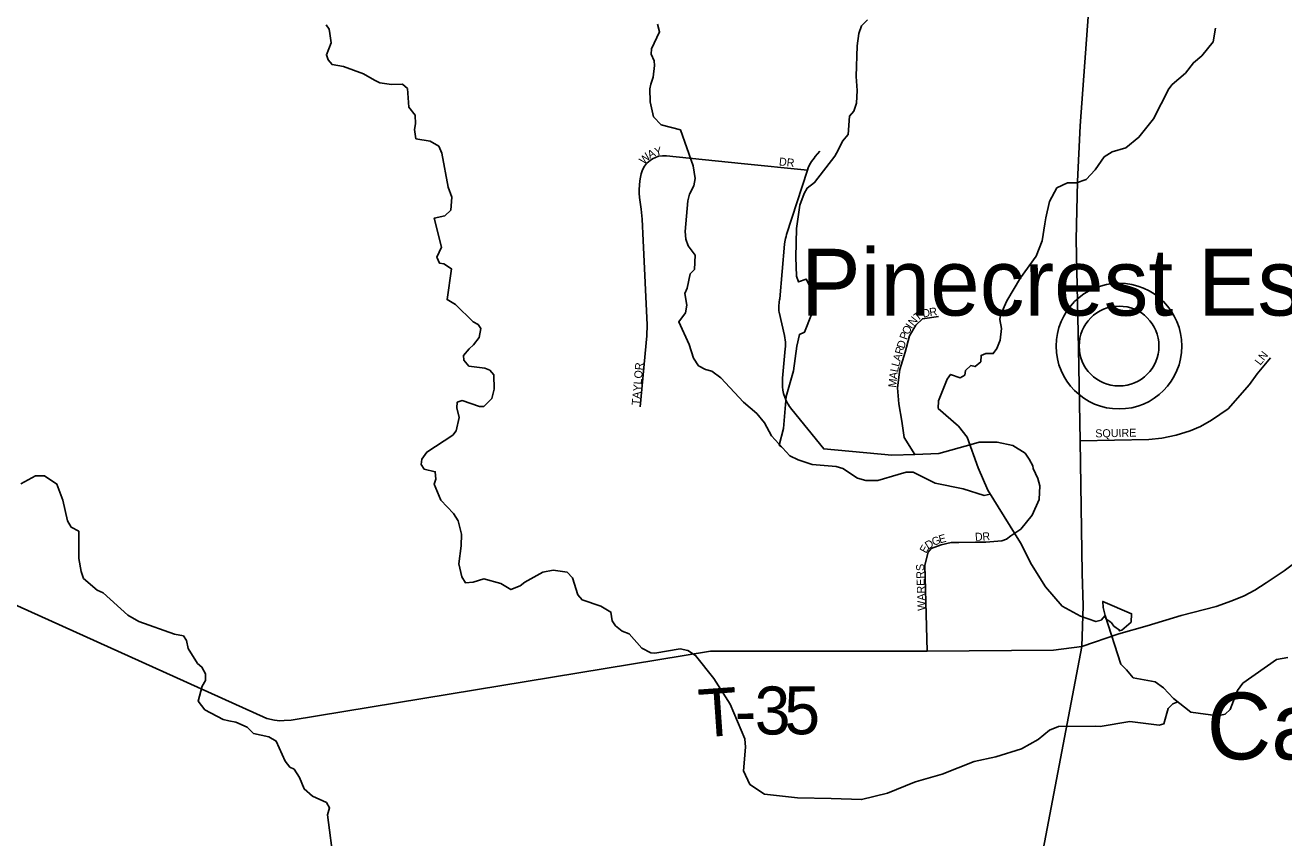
# Model space of a CAD drawing. Extents: x 0 to 40.4, y 0 to 22.
# Drawn here: x 3.509 to 4.998, y 17.952 to 18.913 of the extents above; entities that cross this region are included whole.
import ezdxf

# ---------------------------------------------------------------- set-up
doc = ezdxf.new("R2010")
doc.units = 0
for name, color, linetype in [('GM_X_Minor_Lake', 7, 'Continuous'), ('GM_X_Minor_River', 7, 'Continuous'), ('GM_X_State_Route', 7, 'Continuous'), ('GM_X_Township_Road', 7, 'Continuous'), ('GM_X_Township_Road_Text', 7, 'Continuous'), ('GM_X_Township_Subdivision', 7, 'Continuous'), ('GM_X_Township_Subdivision_Text', 7, 'Continuous'), ('GM_X_Unincorporated', 7, 'Continuous'), ('GM_X_Unincorporated_Text', 7, 'Continuous')]:
    doc.layers.add(name, color=color, linetype=linetype)

msp = doc.modelspace()

# ---------------------------------------------------------------- linework, layer by layer
at = {"layer": 'GM_X_Minor_Lake'}
for points in [[(4.8176, 18.2066), (4.818, 18.2168), (4.7839, 18.2314), (4.7843, 18.2242), (4.7869, 18.2147)], [(4.7869, 18.2147), (4.7877, 18.2109), (4.7922, 18.2075), (4.7941, 18.2059), (4.7971, 18.2021), (4.7998, 18.2002), (4.8035, 18.1979), (4.8035, 18.1964), (4.8066, 18.1972), (4.8176, 18.2066)]]:
    msp.add_lwpolyline(points, dxfattribs=at)
at = {"layer": 'GM_X_Minor_River'}
for points in [[(4.0095, 18.7212), (4.002, 18.7618), (3.9986, 18.7697), (3.9884, 18.7758), (3.9713, 18.7786), (3.9695, 18.7896), (3.971, 18.7964), (3.9703, 18.8066), (3.9631, 18.8161), (3.9613, 18.8381), (3.9556, 18.8431), (3.9423, 18.8428), (3.9287, 18.8447), (3.9223, 18.8481), (3.9094, 18.8554), (3.8855, 18.8642), (3.8722, 18.8665), (3.8677, 18.8722), (3.8655, 18.8779), (3.8712, 18.8923), (3.8697, 18.9033), (3.8686, 18.9083), (3.8652, 18.9136)], [(4.6509, 18.3582), (4.6436, 18.3567), (4.6186, 18.3647), (4.5856, 18.3713), (4.5595, 18.3843), (4.5512, 18.3843), (4.5417, 18.3813), (4.5177, 18.3742), (4.5037, 18.3742), (4.4938, 18.3773), (4.4764, 18.3884), (4.4685, 18.3911), (4.44, 18.3934), (4.4237, 18.3988), (4.4139, 18.4034), (4.392, 18.4274), (4.3837, 18.4426), (4.3746, 18.4536), (4.3591, 18.4669), (4.3319, 18.4958), (4.3213, 18.5038), (4.3141, 18.5058), (4.3058, 18.51), (4.2997, 18.5191), (4.2945, 18.5354), (4.2824, 18.562), (4.2904, 18.5726), (4.292, 18.5817), (4.2897, 18.5957), (4.2924, 18.6018), (4.2959, 18.6189), (4.3008, 18.6238), (4.3017, 18.6408), (4.2933, 18.6519), (4.2907, 18.6598), (4.29, 18.6689), (4.2932, 18.7053), (4.2951, 18.7133), (4.3, 18.7228), (4.3016, 18.7315), (4.2994, 18.7467), (4.2843, 18.7892), (4.2616, 18.7953), (4.2525, 18.8045), (4.2484, 18.8223), (4.2481, 18.8379), (4.2492, 18.8432), (4.2519, 18.8515), (4.2535, 18.8655), (4.2531, 18.8708), (4.2497, 18.8788), (4.2501, 18.8849), (4.2597, 18.9053), (4.2571, 18.9141)], [(4.4039, 18.4143), (4.401, 18.416), (4.4064, 18.4357), (4.4092, 18.4736), (4.418, 18.5043), (4.4219, 18.5334), (4.425, 18.5471), (4.4311, 18.5497), (4.4395, 18.5709), (4.4426, 18.5944), (4.4332, 18.6127), (4.4241, 18.6093), (4.4218, 18.6161), (4.4208, 18.6385), (4.4216, 18.6723), (4.4255, 18.6999), (4.4305, 18.7139), (4.4343, 18.7204), (4.4431, 18.7268), (4.4671, 18.7582), (4.4709, 18.765), (4.4759, 18.776), (4.4827, 18.7835), (4.4843, 18.8052), (4.4896, 18.8112), (4.4927, 18.8207), (4.4935, 18.8358), (4.4921, 18.8525), (4.4933, 18.8886), (4.4953, 18.903), (4.4987, 18.9121), (4.5056, 18.9192)], [(4.7869, 18.2147), (4.782, 18.209), (4.7759, 18.2075), (4.7577, 18.2137), (4.7361, 18.2259), (4.7161, 18.2487), (4.6995, 18.2749), (4.6867, 18.3008), (4.6478, 18.3631), (4.6365, 18.3893), (4.6234, 18.4258), (4.6132, 18.4387), (4.5893, 18.4596), (4.5898, 18.4687), (4.5997, 18.4941), (4.6039, 18.4998), (4.6153, 18.496), (4.6206, 18.499), (4.6217, 18.5047), (4.6278, 18.5103), (4.6328, 18.5092), (4.6396, 18.5148), (4.64, 18.5224), (4.6457, 18.5247), (4.6544, 18.5246), (4.6586, 18.5307), (4.6625, 18.5402), (4.664, 18.5542), (4.6622, 18.5648), (4.6629, 18.5701), (4.6706, 18.5868), (4.6866, 18.614), (4.7053, 18.6398), (4.7122, 18.6579), (4.7153, 18.678), (4.7164, 18.6852), (4.7211, 18.7046), (4.7298, 18.7205), (4.7424, 18.7265), (4.753, 18.7264), (4.7644, 18.7306), (4.7751, 18.7419), (4.7857, 18.7574), (4.7952, 18.7631), (4.8112, 18.7679), (4.8268, 18.7804), (4.8439, 18.8023), (4.8623, 18.8379), (4.8661, 18.8428), (4.8817, 18.8564), (4.8912, 18.8685), (4.9011, 18.8768), (4.9144, 18.8935), (4.9175, 18.9094)], [(4.8726, 18.1127), (4.867, 18.1101), (4.8613, 18.1048), (4.8563, 18.0866), (4.8506, 18.0851), (4.8161, 18.0894), (4.7808, 18.0835), (4.7758, 18.0839), (4.7315, 18.0833), (4.7208, 18.0791), (4.7075, 18.0678), (4.6877, 18.0569), (4.6574, 18.0475), (4.6319, 18.0419), (4.5939, 18.0269), (4.5662, 18.019), (4.5613, 18.0175), (4.5294, 18.0044), (4.4986, 17.9969), (4.4626, 17.9982), (4.4228, 17.9991), (4.3837, 18.0034), (4.3663, 18.0148), (4.3591, 18.0308), (4.3611, 18.0588), (4.3604, 18.0687), (4.3431, 18.1097), (4.3238, 18.1401), (4.3023, 18.1675), (4.2932, 18.1732), (4.2838, 18.1752), (4.2541, 18.1703), (4.2492, 18.1707), (4.2386, 18.1761), (4.2235, 18.1928), (4.2152, 18.1963), (4.2076, 18.2024), (4.2034, 18.2084), (4.202, 18.2187), (4.1902, 18.2259), (4.1679, 18.2332), (4.163, 18.2393), (4.1566, 18.2594), (4.1502, 18.2659), (4.1338, 18.2682), (4.1217, 18.266), (4.1004, 18.254), (4.0947, 18.2498), (4.0837, 18.2453), (4.072, 18.2525), (4.0519, 18.2579), (4.039, 18.2542), (4.0299, 18.2534), (4.0257, 18.2603), (4.022, 18.2759), (4.0247, 18.2971), (4.0251, 18.3107), (4.0214, 18.3267), (4.0157, 18.3354), (4.001, 18.351), (3.9931, 18.37), (3.995, 18.3761), (3.9943, 18.3848), (3.981, 18.3879), (3.9776, 18.3932), (3.9784, 18.3997), (3.9841, 18.408), (4.0149, 18.428), (4.0191, 18.4333), (4.0226, 18.4488), (4.0199, 18.4602), (4.0203, 18.467), (4.026, 18.4689), (4.0465, 18.462), (4.0518, 18.462), (4.0613, 18.4714), (4.064, 18.4824), (4.0637, 18.4995), (4.0588, 18.5048), (4.0527, 18.5071), (4.0341, 18.5098), (4.0281, 18.5167), (4.0277, 18.5224), (4.0342, 18.5303), (4.0395, 18.5348), (4.046, 18.5435), (4.048, 18.5541), (4.0449, 18.5591), (4.0389, 18.5621), (4.0181, 18.5827), (4.0082, 18.5884), (4.0133, 18.6248), (4.0042, 18.6305), (3.9993, 18.6313), (3.9963, 18.6385), (4.0016, 18.6503), (3.993, 18.6848), (4.0055, 18.6874), (4.0128, 18.6942), (4.014, 18.7094), (4.0095, 18.7212)], [(3.8743, 17.9214), (3.8666, 17.9787), (3.8692, 17.987), (3.8655, 17.9935), (3.8492, 18.0008), (3.8393, 18.0095), (3.8337, 18.0232), (3.8273, 18.0327), (3.822, 18.0354), (3.8167, 18.0422), (3.8062, 18.0661), (3.7975, 18.0711), (3.7793, 18.075), (3.7717, 18.0826), (3.7584, 18.0883), (3.7501, 18.0899), (3.7433, 18.0918), (3.7217, 18.1029), (3.7138, 18.1135), (3.7184, 18.1309), (3.7226, 18.1377), (3.7226, 18.1457), (3.7181, 18.1537), (3.7128, 18.1579), (3.7018, 18.1757), (3.7, 18.1852), (3.6962, 18.1906), (3.6856, 18.1925), (3.6435, 18.2074), (3.6307, 18.2151), (3.6015, 18.2413), (3.5943, 18.2448), (3.5781, 18.2585), (3.5754, 18.2668), (3.5725, 18.282), (3.5726, 18.3143), (3.5635, 18.3192), (3.5593, 18.3265), (3.5537, 18.3511), (3.5466, 18.3701), (3.5318, 18.3797), (3.5212, 18.3797), (3.5041, 18.3706)], [(4.92, 18.0959), (4.8882, 18.1005), (4.8678, 18.1165), (4.8557, 18.1291), (4.8458, 18.1363), (4.82, 18.141), (4.8121, 18.1505), (4.8053, 18.157), (4.7869, 18.2147)], [(5.003, 18.165), (4.9893, 18.1628), (4.9498, 18.1345), (4.9433, 18.1258), (4.9345, 18.1034), (4.9288, 18.0981), (4.92, 18.0959)]]:
    msp.add_lwpolyline(points, dxfattribs=at)
at = {"layer": 'GM_X_State_Route'}
msp.add_lwpolyline([(4.8369, 19.8987), (4.804, 19.4399), (4.791, 19.2678), (4.7732, 19.0147), (4.7573, 18.794), (4.7539, 18.7281), (4.7525, 18.6596), (4.7554, 18.5304), (4.7572, 18.4214), (4.7597, 18.2646), (4.7608, 18.2263), (4.759, 18.178), (4.7164, 17.9544), (4.6792, 17.7593)], dxfattribs=at)
at = {"layer": 'GM_X_Township_Road'}
for points in [[(6.1264, 18.8144), (5.7095, 18.6233), (5.6523, 18.5981), (5.3968, 18.4728), (5.2841, 18.4312), (5.2746, 18.429), (5.2643, 18.4248), (5.2567, 18.4218), (5.2483, 18.4173), (5.2376, 18.4113), (5.1965, 18.393), (5.0945, 18.335), (5.0605, 18.3088), (5.0561, 18.3105), (4.9987, 18.2677), (4.9774, 18.2534), (4.964, 18.2447), (4.9511, 18.238), (4.9366, 18.2319), (4.9183, 18.2252), (4.8769, 18.2146), (4.8363, 18.2023), (4.8029, 18.1929), (4.759, 18.178)], [(4.759, 18.178), (4.7255, 18.1738), (4.5761, 18.1725), (4.32, 18.1723), (3.8239, 18.0909), (3.8155, 18.0906), (3.8102, 18.0902), (3.8041, 18.091), (3.795, 18.0929), (3.352, 18.2928), (3.2148, 18.3905), (2.8672, 18.5093), (2.7354, 18.5128), (2.6, 18.5025)]]:
    msp.add_lwpolyline(points, dxfattribs=at)
at = {"layer": 'GM_X_Township_Subdivision'}
for points in [[(4.5761, 18.1725), (4.5734, 18.2742), (4.5773, 18.2895), (4.5811, 18.2939), (4.5926, 18.2984), (4.6047, 18.301), (4.6136, 18.301), (4.6334, 18.3016), (4.6455, 18.3016), (4.6647, 18.3029), (4.6701, 18.3048), (4.6752, 18.3089), (4.687, 18.3169), (4.7004, 18.3335), (4.7087, 18.352), (4.7094, 18.368), (4.7071, 18.3769), (4.7017, 18.3884), (4.7011, 18.3919), (4.6969, 18.3996), (4.6921, 18.4069), (4.6775, 18.4158), (4.6589, 18.4197), (4.6379, 18.4197), (4.6283, 18.4171), (4.59, 18.4063), (4.5616, 18.4053), (4.5345, 18.4043), (4.4538, 18.4117), (4.4159, 18.4585), (4.4133, 18.4619), (4.4117, 18.4645), (4.4107, 18.4662), (4.4089, 18.4699), (4.4077, 18.4731), (4.4064, 18.4773), (4.4056, 18.4811), (4.405, 18.4852), (4.4049, 18.4906), (4.4052, 18.4956), (4.4082, 18.5301), (4.4085, 18.5329), (4.4085, 18.5353), (4.4085, 18.5379), (4.4083, 18.5406), (4.4079, 18.5433), (4.4074, 18.546), (4.4011, 18.5735), (4.4009, 18.5749), (4.4009, 18.576), (4.4008, 18.5776), (4.4008, 18.5796), (4.4009, 18.582), (4.401, 18.5839), (4.4013, 18.5859), (4.4016, 18.588), (4.4019, 18.5894), (4.4075, 18.6539), (4.4079, 18.6567), (4.4082, 18.6587), (4.4087, 18.6608), (4.4092, 18.6629), (4.4099, 18.6652), (4.4348, 18.7416), (4.4356, 18.7444), (4.4362, 18.7462), (4.4383, 18.7497), (4.4395, 18.7516), (4.4408, 18.7537), (4.4424, 18.7558), (4.4438, 18.7576), (4.4494, 18.764)], [(4.4348, 18.7416), (4.3563, 18.7494), (4.2678, 18.7583), (4.2632, 18.7584), (4.2585, 18.7579), (4.2548, 18.7566), (4.2512, 18.755), (4.2469, 18.7519), (4.2441, 18.7492), (4.2419, 18.7464), (4.2394, 18.742), (4.2379, 18.7372), (4.237, 18.7334), (4.2362, 18.7288), (4.2354, 18.7186), (4.2355, 18.7142), (4.2357, 18.7092), (4.238, 18.6952), (4.239, 18.6834), (4.2401, 18.6582), (4.245, 18.5584), (4.2446, 18.5454), (4.2367, 18.4615)], [(4.5616, 18.4053), (4.5489, 18.4254), (4.5463, 18.4445), (4.5425, 18.465), (4.5412, 18.4841), (4.5438, 18.5058), (4.5502, 18.5262), (4.5553, 18.5454), (4.5629, 18.5581), (4.5706, 18.5658), (4.5897, 18.5683)], [(4.7572, 18.4214), (4.8384, 18.4228), (4.8539, 18.4246), (4.8706, 18.4279), (4.8872, 18.4333), (4.8994, 18.4384), (4.9124, 18.4456), (4.9323, 18.4593), (4.9575, 18.488), (4.9667, 18.5006), (4.9822, 18.5195)]]:
    msp.add_lwpolyline(points, dxfattribs=at)
at = {"layer": 'GM_X_Unincorporated'}
for radius in [0.0744, 0.0472]:
    msp.add_circle((4.8032, 18.5334), radius, dxfattribs=at)

# ---------------------------------------------------------------- texts
at = {"layer": 'GM_X_Township_Road_Text'}
for s, rotation, p in [('T', 3.9974, (4.3076, 18.0703)), ('3', 0.5412, (4.3724, 18.0737)), ('5', 0.3903, (4.4074, 18.074)), ('-', 1.0929, (4.3492, 18.0733))]:
    msp.add_text(s, height=0.0568, rotation=rotation, dxfattribs=at).set_placement(p)
at = {"layer": 'GM_X_Township_Subdivision_Text'}
for s, rotation, p in [('W', 44.5483, (4.241, 18.7477)), ('A', 26.7019, (4.2481, 18.7548)), ('Y', 13.7023, (4.255, 18.7584)), ('DR', 353.9832, (4.4005, 18.7472)), ('T', 38.4764, (4.565, 18.5626)), ('D', 11.9787, (4.5715, 18.567)), ('R', 8.8754, (4.5795, 18.5687)), ('O', 61.1959, (4.554, 18.5461)), ('I', 57.0861, (4.5579, 18.5532)), ('N', 50.603, (4.56, 18.5565)), ('D', 73.6253, (4.549, 18.5299)), ('P', 70.5024, (4.552, 18.5402)), ('R', 73.6555, (4.5468, 18.5227)), ('LN', 51.8483, (4.9703, 18.5099)), ('TAYLOR', 84.8967, (4.236, 18.4631)), ('L', 74.3399, (4.5427, 18.5083)), ('A', 73.6462, (4.5445, 18.5147)), ('M', 83.2997, (4.5394, 18.4839)), ('A', 83.2736, (4.5405, 18.4939)), ('L', 79.0061, (4.5415, 18.502)), ('SQUIRE', 1.1452, (4.7752, 18.4253)), ('D', 32.793, (4.5773, 18.2925)), ('G', 22.6131, (4.5839, 18.2968)), ('E', 15.0898, (4.5913, 18.2999)), ('D', 0.6558, (4.6328, 18.303)), ('R', 4.572, (4.6419, 18.3032)), ('E', 60.7702, (4.5749, 18.2875)), ('WARERS', 91.9739, (4.5744, 18.2204))]:
    msp.add_text(s, height=0.00947, rotation=rotation, dxfattribs=at).set_placement(p)
at = {"layer": 'GM_X_Unincorporated_Text'}
for s, height, p in [('Pinecrest Estates', 0.078977, (4.427, 18.5695)), ('Canyon', 0.07898, (4.907, 18.0445))]:
    msp.add_text(s, height=height, rotation=0, dxfattribs=at).set_placement(p)

doc.saveas('drawing.dxf')
